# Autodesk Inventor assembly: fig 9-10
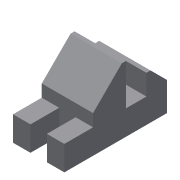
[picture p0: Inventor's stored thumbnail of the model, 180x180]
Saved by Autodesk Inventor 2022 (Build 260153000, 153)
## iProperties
Created: 2002-01
Part Number: fig 9-10
Document SubType Name: Assembly
Designer: ***
Control State: 0
Master: False
Checked Out: False
Shininess: 64.0
Length Units: 11269
Angle Units: 11279
Time Units: 11290
Mass Units: 11283
Length Display Precision: 3
Angle Display Precision: 2
Density: 0.0
Volumn: 0.0
Area: 0.0
PropertySet Name: Model Information
Author: ***
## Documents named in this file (3)
- D:\PROJECTS_2021\Resources\Part Files\c09_Inv_2022_prt\fig 9-10.iam
- D:\PROJECTS_2021\Resources\Part Files\c09_Inv_2022_prt\Part3.ipt
- D:\PROJECTS_2021\Resources\Part Files\c09_Inv_2022_prt\Part4.ipt
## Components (2 placed, 2 different names)
1. Part3:1
2. Part4:1
